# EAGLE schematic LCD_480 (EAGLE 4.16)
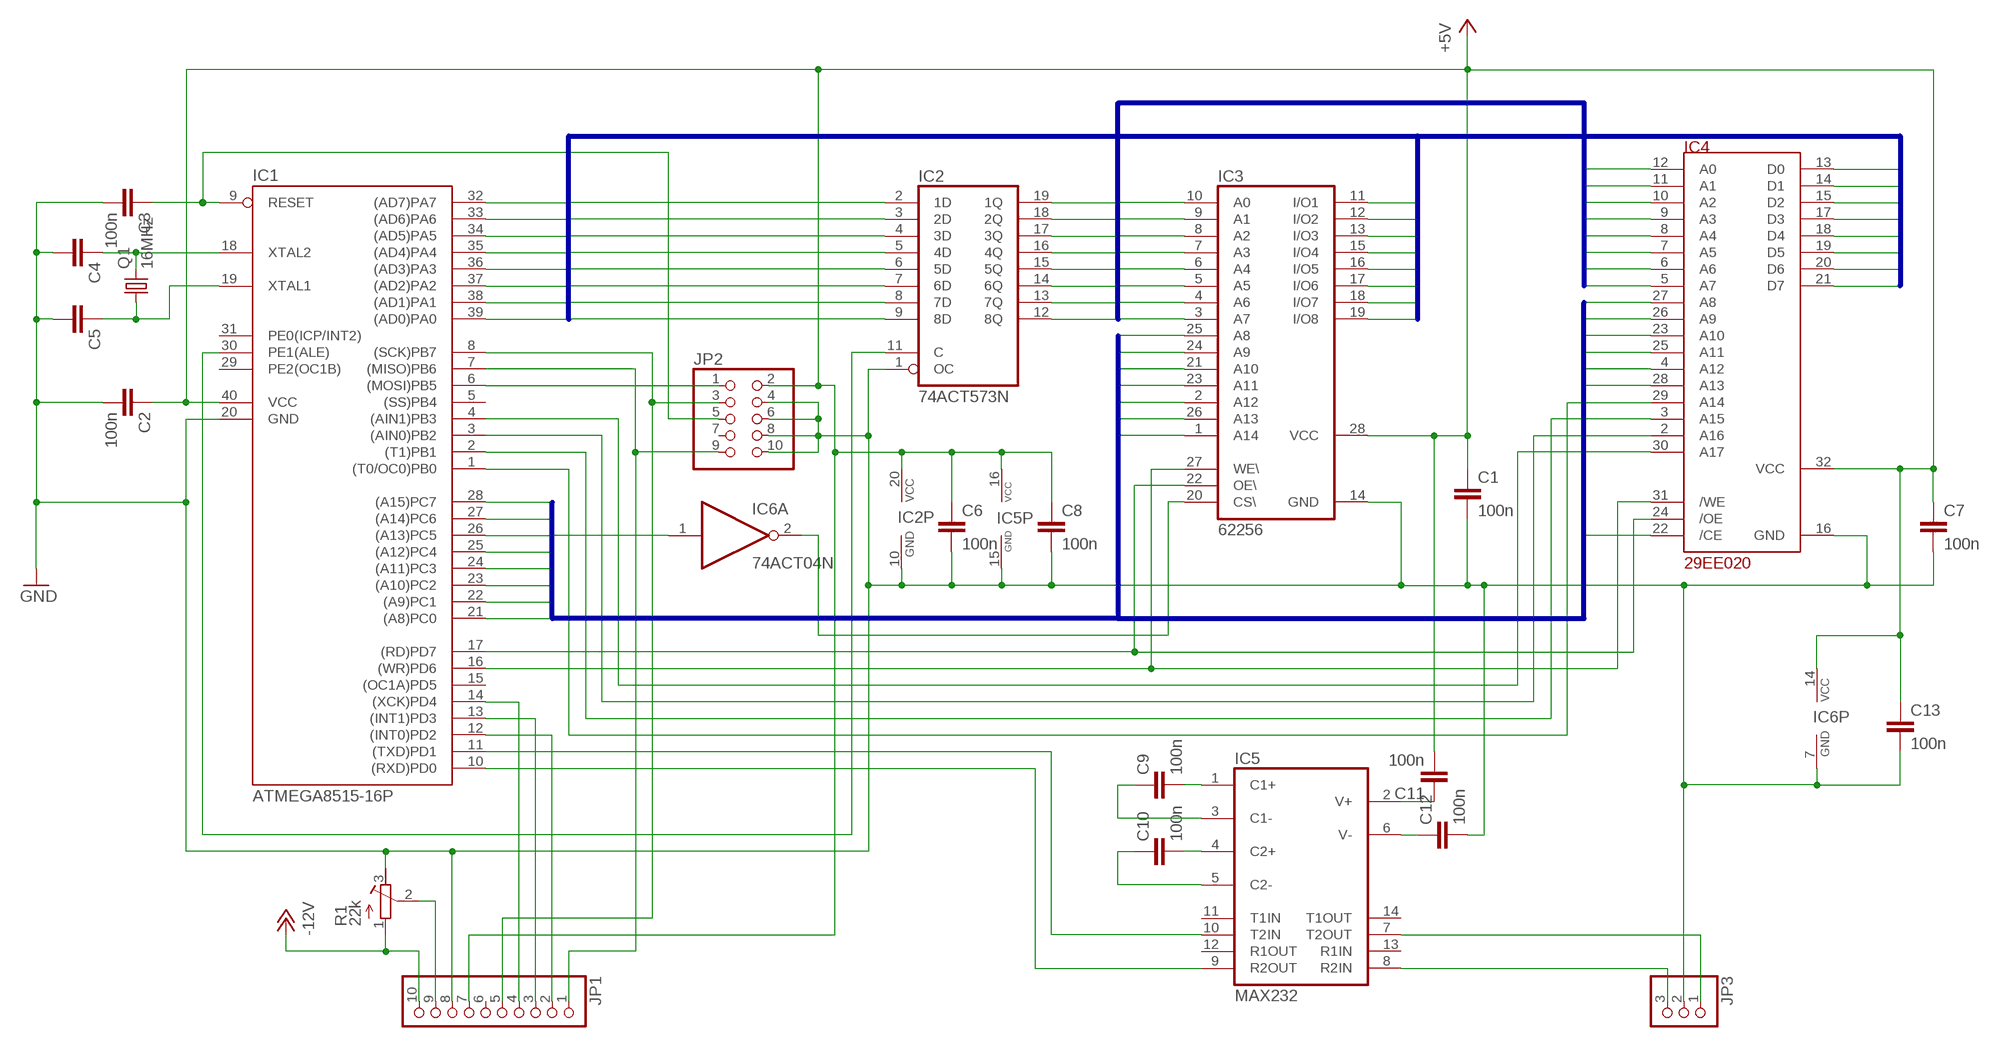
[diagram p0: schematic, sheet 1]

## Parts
C1  100n  C-EU025-025X050  [C025-025X050]
C2  100n  C-EU025-025X050  [C025-025X050]
C3  100n  C-EU025-025X050  [C025-025X050]
C4  C-EU025-025X050  [C025-025X050]
C5  C-EU025-025X050  [C025-025X050]
C6  100n  C-EU025-025X050  [C025-025X050]
C7  100n  C-EU025-025X050  [C025-025X050]
C8  100n  C-EU025-025X050  [C025-025X050]
C9  100n  C-EU025-025X050  [C025-025X050]
C10  100n  C-EU025-025X050  [C025-025X050]
C11  100n  C-EU025-025X050  [C025-025X050]
C12  100n  C-EU025-025X050  [C025-025X050]
C13  100n  C-EU025-025X050  [C025-025X050]
IC1  ATMEGA8515-16P  [DIL40]
IC2  74ACT573N  [DIL20]
IC3  62256  43256AC  [DIL28-6]
IC4  29EE020  [DIL32]
IC5  MAX232  [DIL16]
IC6  74ACT04N  [DIL14]
JP1  PINHD-1X10  [1X10]
JP2  PINHD-2X5  [2X05]
JP3  PINHD-1X3  [1X03]
Q1  16MHz  CRYSTALHC49S  [HC49/S]
R1  22k  R-TRIMM3339P  [RTRIM3339P]

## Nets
+5V: C1.1 C2.1 C6.1 C7.1 C8.1 C11.2 C13.1 IC1.40(VCC) IC2.20(VCC) IC4.32(VCC) IC5.16(VCC) IC6.14(P:VCC) JP1.7 JP2.2
-12V: JP1.10 R1.1(E)
A0: IC2.19(1Q) IC3.10(A0) IC4.12(A0)
A1: IC2.18(2Q) IC3.9(A1) IC4.11(A1)
A2: IC2.17(3Q) IC3.8(A2) IC4.10(A2)
A3: IC2.16(4Q) IC3.7(A3) IC4.9(A3)
A4: IC2.15(5Q) IC3.6(A4) IC4.8(A4)
A5: IC2.14(6Q) IC3.5(A5) IC4.7(A5)
A6: IC2.13(7Q) IC3.4(A6) IC4.6(A6)
A7: IC2.12(8Q) IC3.3(A7) IC4.5(A7)
A8: IC1.21((A8)PC0) IC3.25(A8) IC4.27(A8)
A9: IC1.22((A9)PC1) IC3.24(A9) IC4.26(A9)
A10: IC1.23((A10)PC2) IC3.21(A10) IC4.23(A10)
A11: IC1.24((A11)PC3) IC3.23(A11) IC4.25(A11)
A12: IC1.25((A12)PC4) IC3.2(A12) IC4.4(A12)
A13: IC1.26((A13)PC5) IC3.26(A13) IC4.28(A13)
A14: IC1.27((A14)PC6) IC3.1(A14)
A15: IC1.28((A15)PC7) IC4.22(/CE) IC6.1(A:I)
AD0: IC1.39((AD0)PA0) IC2.2(1D) IC3.11(I/O1) IC4.13(D0)
AD1: IC1.38((AD1)PA1) IC2.3(2D) IC3.12(I/O2) IC4.14(D1)
AD2: IC1.37((AD2)PA2) IC2.4(3D) IC3.13(I/O3) IC4.15(D2)
AD3: IC1.36((AD3)PA3) IC2.5(4D) IC3.15(I/O4) IC4.17(D3)
AD4: IC1.35((AD4)PA4) IC2.6(5D) IC3.16(I/O5) IC4.18(D4)
AD5: IC1.34((AD5)PA5) IC2.7(6D) IC3.17(I/O6) IC4.19(D5)
AD6: IC1.33((AD6)PA6) IC2.8(7D) IC3.18(I/O7) IC4.20(D6)
AD7: IC1.32((AD7)PA7) IC2.9(8D) IC3.19(I/O8) IC4.21(D7)
GND: C1.2 C2.2 C3.2 C4.2 C5.2 C6.2 C7.2 C8.2 C12.2 C13.2 IC1.20(GND) IC2.1(OC) IC2.10(GND) IC4.16(GND) IC5.15(GND) IC6.7(P:GND) JP1.8 JP2.4 JP2.6 JP2.8 JP2.10 JP3.2 R1.3(A)
N$1: IC1.1((T0/OC0)PB0) IC4.29(A14)
N$2: IC1.2((T1)PB1) IC4.3(A15)
N$3: IC1.3((AIN0)PB2) IC4.2(A16)
N$4: IC1.4((AIN1)PB3) IC4.30(A17)
N$5: C10.2 IC5.4(C2+)
N$6: IC1.12((INT0)PD2) JP1.2
N$7: IC1.13((INT1)PD3) JP1.3
N$8: IC1.14((XCK)PD4) JP1.4
N$9: IC1.17((RD)PD7) IC3.22(OE\) IC4.24(/OE)
N$10: IC1.16((WR)PD6) IC3.27(WE\) IC4.31(/WE)
N$11: C3.1 IC1.9(RESET) JP2.5
N$12: C4.1 IC1.18(XTAL2) Q1.2
N$13: C5.1 IC1.19(XTAL1) Q1.1
N$14: C9.2 IC5.1(C1+)
N$15: IC1.30(PE1(ALE)) IC2.11(C)
N$16: IC1.6((MOSI)PB5) JP2.1
N$17: IC1.8((SCK)PB7) JP1.5 JP2.3
N$18: IC1.7((MISO)PB6) JP1.1 JP2.9
N$19: C9.1 IC5.3(C1-)
N$20: C10.1 IC5.5(C2-)
N$21: C11.1 IC5.2(V+)
N$22: JP1.9 R1.2(S)
N$23: C12.1 IC5.6(V-)
N$24: IC1.10((RXD)PD0) IC5.9(R2OUT)
N$25: IC1.11((TXD)PD1) IC5.10(T2IN)
N$26: IC5.8(R2IN) JP3.3
N$27: IC5.7(T2OUT) JP3.1
N$28: IC3.20(CS\) IC6.2(A:O)
Unconnected: IC1.5((SS)PB4) IC1.15((OC1A)PD5) IC1.29(PE2(OC1B)) IC1.31(PE0(ICP/INT2)) IC5.11(T1IN) IC5.12(R1OUT) IC5.13(R1IN) IC5.14(T1OUT) IC6.3(B:I) IC6.4(B:O) IC6.5(C:I) IC6.6(C:O) IC6.8(D:O) IC6.9(D:I) IC6.10(E:O) IC6.11(E:I) IC6.12(F:O) IC6.13(F:I) JP1.6 JP2.7

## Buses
AD[0..7]
A[8..15]
A[0..7]

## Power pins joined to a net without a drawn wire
GND: IC3.14(GND)
VCC: IC3.28(VCC)

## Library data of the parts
C1-C13 = rcl:C-EU: CAPACITOR, European symbol
IC1 = avr:ATMEGA8515*P: MICROCONTROLLER 8 Kbytes FLASH 512 bytes SRAM 512 bytes EEPROM USART
IC2 = 74xx-eu:74*573: 8-bit D latch BUS DRIVER
IC3 = memory-nec:43256AC: MEMORY
IC4 = memory:29EE020
IC5 = maxim:MAX232: RS232 TRANSEIVER
IC6 = 74xx-eu:74*04: Hex INVERTER
JP1 = pinhead:PINHD-1X10: PIN HEADER
JP2 = pinhead:PINHD-2X5: PIN HEADER
JP3 = pinhead:PINHD-1X3: PIN HEADER
Q1 = crystal:CRYSTAL: CRYSTAL
R1 = rcl:R-TRIMM: Trimm resistor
